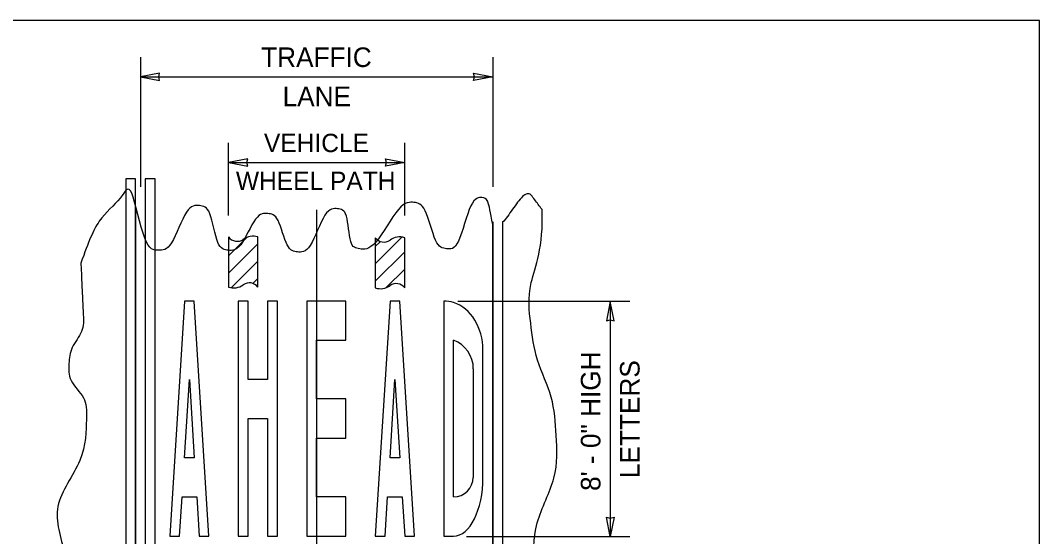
# Model space of a CAD drawing. Extents: x 99862 to 103151, y 100000 to 105076.
# Drawn here: x 102318 to 103151, y 104654 to 105076 of the extents above; entities that cross this region are included whole.
import ezdxf

# ---------------------------------------------------------------- set-up
doc = ezdxf.new("R2010")
doc.units = 0
for name, color, linetype in [('Level 1', 7, 'Continuous'), ('Level 15', 7, 'Continuous'), ('Level 2', 7, 'Continuous'), ('Level 20', 7, 'Continuous'), ('Level 3', 7, 'Continuous'), ('Level 6', 7, 'Continuous'), ('Level 60', 7, 'Continuous'), ('Level 8', 7, 'Continuous')]:
    doc.layers.add(name, color=color, linetype=linetype)

msp = doc.modelspace()

# ---------------------------------------------------------------- linework, layer by layer
at = {"layer": 'Level 1'}
msp.add_lwpolyline([(99862, 102999.5), (103151, 102999.5), (103151, 105075.5), (99862, 105075.5)], close=True, dxfattribs=at)
at = {"layer": 'Level 15'}
for p, q in [((102416.06, 105045.42), (102416.06, 104939.66)), ((102704.06, 105045.42), (102704.06, 104939.66)), ((102416.06, 105029.42), (102704.06, 105029.42)), ((102488.06, 104916.16), (102488.06, 104975.42)), ((102632.06, 104916.16), (102632.06, 104975.42)), ((102488.06, 104959.42), (102632.06, 104959.42)), ((102560.06, 104920.92), (102560.06, 104556.98)), ((102675.56, 104846.3), (102816.06, 104846.3)), ((102800.06, 104845.98), (102800.06, 104653.98)), ((102682.56, 104654), (102816.06, 104654))]:
    msp.add_line(p, q, dxfattribs=at)
for points in [[(102416.06, 105029.42), (102431.79, 105026.34), (102431.06, 105029.42), (102431.79, 105032.51)], [(102704.06, 105029.42), (102688.34, 105026.34), (102689.06, 105029.42), (102688.34, 105032.51)], [(102488.06, 104959.42), (102503.79, 104956.34), (102503.06, 104959.42), (102503.79, 104962.51)], [(102632.06, 104959.42), (102616.34, 104956.34), (102617.06, 104959.42), (102616.34, 104962.51)], [(102800.06, 104845.98), (102796.98, 104830.25), (102800.06, 104830.98), (102803.15, 104830.25)], [(102800.06, 104653.98), (102796.98, 104669.7), (102800.06, 104668.97), (102803.15, 104669.7)]]:
    msp.add_lwpolyline(points, close=True, dxfattribs=at)
at = {"layer": 'Level 2'}
for points in [[(102412.06, 104946.11), (102404.06, 104946.11), (102404.06, 104152.38)], [(102412.06, 104152.38), (102412.06, 104946.11)], [(102428.06, 104946.11), (102420.06, 104946.11), (102420.06, 104152.38)], [(102428.06, 104152.38), (102428.06, 104946.11)]]:
    msp.add_lwpolyline(points, dxfattribs=at)
at = {"layer": 'Level 3'}
msp.add_line((102704.06, 104176.2), (102704.06, 104908.92), dxfattribs=at)
for points in [[(102744.37, 104920.98), (102744.17, 104921.25), (102743.44, 104922.22), (102742.72, 104923.19), (102741.99, 104924.16), (102741.27, 104925.13), (102740.55, 104926.1), (102739.82, 104927.07), (102739.1, 104928.04), (102738.37, 104929.01), (102737.65, 104929.98), (102736.92, 104930.95), (102736.2, 104931.92), (102735.46, 104932.83), (102734.69, 104933.46), (102733.89, 104933.84), (102733.05, 104933.97), (102732.18, 104933.87), (102731.28, 104933.56), (102730.35, 104933.06), (102729.4, 104932.39), (102728.43, 104931.55), (102727.44, 104930.58), (102726.43, 104929.48), (102725.42, 104928.27), (102724.39, 104926.97), (102723.35, 104925.6), (102722.3, 104924.18), (102721.26, 104922.71), (102720.21, 104921.22), (102719.16, 104919.73), (102718.12, 104918.25), (102717.09, 104916.81), (102716.06, 104915.4), (102715.05, 104914.07), (102714.05, 104912.81), (102713.07, 104911.65), (102712.1, 104910.61), (102712.06, 104910.57)], [(102712.06, 104910.57), (102712.06, 104170.68)]]:
    msp.add_lwpolyline(points, dxfattribs=at)
for points in [[(102704.06, 104908.92), (102702.11, 104918.72), (102700.16, 104930.36), (102695.98, 104930.67), (102686.22, 104931.4), (102675.89, 104887.7), (102666.07, 104889.05), (102657.28, 104890.26), (102648.88, 104925.74), (102640.05, 104926.77), (102628.67, 104928.09), (102606.85, 104887.33), (102594.53, 104889.05), (102586.89, 104890.12), (102585.45, 104920.58), (102577.62, 104921.57), (102567.26, 104922.86), (102554.42, 104885.31), (102544.13, 104886.45), (102535.82, 104887.36), (102528.82, 104916.89), (102520.39, 104917.66), (102510.9, 104918.53), (102497.33, 104886.91), (102487.88, 104887.75), (102478.62, 104888.57), (102473.5, 104923.21), (102464.47, 104924.17), (102454.1, 104925.26), (102441.09, 104887.69), (102430.65, 104887.75), (102419.81, 104887.81), (102407.94, 104946.82), (102402.04, 104930.67), (102380.42, 104912.89), (102373.91, 104895.12), (102367.41, 104877.34)], [(102743.72, 104172.94), (102743.46, 104178.25), (102743.11, 104184.18), (102742.83, 104191.13), (102741.44, 104216.72), (102735.08, 104242.39), (102735.02, 104267.87), (102734.98, 104287.88), (102749.55, 104306.49), (102750.63, 104326.4), (102752.85, 104367.3), (102735.14, 104409.1), (102736.32, 104449.96), (102737.28, 104482.98), (102754.25, 104515.98), (102754.53, 104548.81), (102754.75, 104574.48), (102738.2, 104599.88), (102737.62, 104625.55), (102736.82, 104665.9), (102757.9, 104701.76), (102755.83, 104737.2), (102754.05, 104767.8), (102738.79, 104797.9), (102735.02, 104828.25), (102731.29, 104858.36), (102745.71, 104890.29), (102744.37, 104920.98)], [(102367.41, 104877.34), (102368.06, 104863.25), (102368.71, 104849.16), (102369.36, 104835.07), (102370, 104821.3), (102358.55, 104808.51), (102357.65, 104795.4), (102356.69, 104781.26), (102372.14, 104767.33), (102371.96, 104753.13), (102371.49, 104716.03), (102340.94, 104678.76), (102356.51, 104640.63), (102356.96, 104597.91), (102378.76, 104560.19), (102378.62, 104522.47), (102378.44, 104469.14), (102346.06, 104415.82), (102347.41, 104362.49), (102348.23, 104330.01), (102372.35, 104298.72), (102371.8, 104266.24), (102371.26, 104234.85), (102359.41, 104202.95), (102357.81, 104164.79), (102357.74, 104163.56), (102357.66, 104162.36), (102357.58, 104161.2)]]:
    msp.add_open_spline(points, degree=3, dxfattribs=at)
at = {"layer": 'Level 6'}
for p, q in [((102712.06, 104911.16), (102712.06, 104169.99)), ((102488.06, 104898.63), (102488.06, 104857.63)), ((102488.06, 104883.24), (102503.02, 104898.19)), ((102488.06, 104897.38), (102488.67, 104897.99)), ((102608.06, 104876.73), (102629.77, 104898.44)), ((102608.06, 104898.03), (102608.06, 104857.03)), ((102632.06, 104857.03), (102632.06, 104898.03)), ((102488.06, 104869.09), (102512.06, 104893.09)), ((102608.06, 104890.87), (102612.2, 104895.01)), ((102608.06, 104862.59), (102632.06, 104886.59)), ((102490.31, 104857.2), (102512.06, 104878.95)), ((102617, 104857.38), (102632.06, 104872.45)), ((102507.91, 104860.66), (102512.06, 104864.81)), ((102631.44, 104857.68), (102632.06, 104858.3))]:
    msp.add_line(p, q, dxfattribs=at)
for points in [[(102404.06, 104933.83), (102404.06, 104178.98)], [(102412.06, 104921.59), (102412.06, 104177.45)], [(102704.06, 104910.92), (102704.06, 104175.77)], [(102420.06, 104902.86), (102420.06, 104172.39)], [(102512.06, 104857.63), (102512.06, 104898.63)], [(102428.06, 104162.93), (102428.06, 104889.29)]]:
    msp.add_lwpolyline(points, dxfattribs=at)
for centre, radius, start, end in [((102495.09, 104903.78), 8.71, 216.245, 304.83036), ((102508.06, 104885.63), 13.6, 72.89727, 126.02737), ((102615.09, 104903.18), 8.71, 216.245, 304.83036), ((102628.06, 104885.03), 13.6, 72.89727, 126.02737), ((102492.13, 104870.21), 13.23, 252.07882, 306.84583), ((102505.04, 104852.48), 8.71, 36.245, 124.83036), ((102612.13, 104869.61), 13.23, 252.07882, 306.84583), ((102625.04, 104851.88), 8.71, 36.245, 124.83036)]:
    msp.add_arc(centre, radius, start, end, dxfattribs=at)
at = {"layer": 'Level 60'}
msp.add_line((103151, 105075.5), (103151, 105075.5), dxfattribs=at)
at = {"layer": 'Level 8'}
for p, q in [((102452.06, 104846.3), (102440.06, 104654.3)), ((102460.06, 104846.3), (102452.06, 104846.3)), ((102472.06, 104654.3), (102460.06, 104846.3)), ((102620.06, 104846.3), (102608.06, 104654.3)), ((102628.06, 104846.3), (102620.06, 104846.3)), ((102640.06, 104654.3), (102628.06, 104846.3)), ((102664.06, 104846.3), (102664.06, 104791.05)), ((102672.06, 104791.05), (102672.06, 104814.3)), ((102664.06, 104791.05), (102664.06, 104790.3)), ((102664.06, 104790.3), (102664.06, 104710.3)), ((102672.06, 104790.3), (102672.06, 104791.05)), ((102672.06, 104710.3), (102672.06, 104790.3)), ((102688.1, 104791.05), (102688.06, 104790.3)), ((102688.06, 104790.3), (102688.06, 104710.3)), ((102452.06, 104718.3), (102456.06, 104782.3)), ((102456.06, 104782.3), (102460.06, 104718.3)), ((102620.06, 104718.3), (102624.06, 104782.3)), ((102624.06, 104782.3), (102628.06, 104718.3)), ((102460.06, 104718.3), (102452.06, 104718.3)), ((102628.06, 104718.3), (102620.06, 104718.3)), ((102664.06, 104710.3), (102664.06, 104709.3)), ((102664.06, 104709.3), (102664.06, 104654.3)), ((102672.06, 104709.3), (102672.06, 104710.3)), ((102672.06, 104686.3), (102672.06, 104709.3)), ((102688.06, 104710.3), (102688.06, 104709.3)), ((102688.06, 104709.3), (102688.06, 104702.3)), ((102448.06, 104654.3), (102450.06, 104686.3)), ((102450.06, 104686.3), (102462.06, 104686.3)), ((102462.06, 104686.3), (102464.06, 104654.3)), ((102616.06, 104654.3), (102618.06, 104686.3)), ((102618.06, 104686.3), (102630.06, 104686.3)), ((102630.06, 104686.3), (102632.06, 104654.3)), ((102440.06, 104654.3), (102448.06, 104654.3)), ((102464.06, 104654.3), (102472.06, 104654.3)), ((102608.06, 104654.3), (102616.06, 104654.3)), ((102632.06, 104654.3), (102640.06, 104654.3)), ((102664.06, 104654.3), (102672.06, 104654.3))]:
    msp.add_line(p, q, dxfattribs=at)
for points in [[(102448.06, 104654.3), (102450.06, 104686.3), (102462.06, 104686.3), (102464.06, 104654.3), (102472.06, 104654.3), (102460.06, 104846.3), (102452.06, 104846.3), (102440.06, 104654.3), (102448.06, 104654.3)], [(102452.06, 104846.3), (102440.06, 104654.3), (102448.06, 104654.3), (102450.06, 104686.3), (102462.06, 104686.3), (102464.06, 104654.3), (102472.06, 104654.3), (102460.06, 104846.3), (102452.06, 104846.3)], [(102520.06, 104846.3), (102520.06, 104782.3), (102504.06, 104782.3), (102504.06, 104846.3), (102496.06, 104846.3), (102496.06, 104654.3), (102504.06, 104654.3), (102504.06, 104750.3), (102520.06, 104750.3), (102520.06, 104654.3), (102528.06, 104654.3), (102528.06, 104846.3), (102520.06, 104846.3)], [(102528.06, 104846.3), (102520.06, 104846.3), (102520.06, 104782.3), (102504.06, 104782.3), (102504.06, 104846.3), (102496.06, 104846.3), (102496.06, 104654.3), (102504.06, 104654.3), (102504.06, 104750.3), (102520.06, 104750.3), (102520.06, 104654.3), (102528.06, 104654.3), (102528.06, 104846.3)], [(102560.06, 104686.3), (102560.06, 104734.3), (102584.06, 104734.3), (102584.06, 104766.3), (102560.06, 104766.3), (102560.06, 104814.3), (102584.06, 104814.3), (102584.06, 104846.3), (102560.06, 104846.3), (102556.06, 104846.3), (102552.06, 104846.3), (102552.06, 104654.3), (102558.06, 104654.3), (102560.06, 104654.3), (102584.06, 104654.3), (102584.06, 104686.3), (102560.06, 104686.3)], [(102558.06, 104654.3), (102560.06, 104654.3), (102584.06, 104654.3), (102584.06, 104686.3), (102560.06, 104686.3), (102560.06, 104734.3), (102584.06, 104734.3), (102584.06, 104766.3), (102560.06, 104766.3), (102560.06, 104814.3), (102584.06, 104814.3), (102584.06, 104846.3), (102560.06, 104846.3), (102556.06, 104846.3), (102552.06, 104846.3), (102552.06, 104654.3), (102558.06, 104654.3)], [(102616.06, 104654.3), (102618.06, 104686.3), (102630.06, 104686.3), (102632.06, 104654.3), (102640.06, 104654.3), (102628.06, 104846.3), (102620.06, 104846.3), (102608.06, 104654.3), (102616.06, 104654.3)], [(102630.06, 104686.3), (102632.06, 104654.3), (102640.06, 104654.3), (102628.06, 104846.3), (102620.06, 104846.3), (102608.06, 104654.3), (102616.06, 104654.3), (102618.06, 104686.3), (102630.06, 104686.3)], [(102664.06, 104846.3), (102664.06, 104791.05), (102664.06, 104790.3), (102664.06, 104710.3), (102664.06, 104709.3), (102664.06, 104654.3), (102672.06, 104654.3)], [(102664.06, 104846.3), (102664.06, 104791.05), (102664.06, 104790.3), (102664.06, 104710.3)], [(102672.06, 104686.3), (102672.06, 104709.3), (102672.06, 104710.3), (102672.06, 104790.3), (102672.06, 104791.05), (102672.06, 104814.3)], [(102672.06, 104686.3), (102672.06, 104709.3), (102672.06, 104710.3), (102672.06, 104790.3), (102672.06, 104791.05), (102672.06, 104814.3)], [(102696.06, 104702.3), (102696.06, 104709.3), (102696.06, 104710.3), (102696.06, 104790.3), (102696.06, 104791.05), (102696.06, 104806.3)], [(102688.1, 104791.05), (102688.06, 104790.3), (102688.06, 104710.3), (102688.06, 104709.3), (102688.06, 104702.3)], [(102688.1, 104791.05), (102688.06, 104790.3), (102688.06, 104710.3), (102688.06, 104709.3), (102688.06, 104702.3)], [(102456.06, 104782.3), (102460.06, 104718.3), (102452.06, 104718.3), (102456.06, 104782.3)], [(102452.06, 104718.3), (102456.06, 104782.3), (102460.06, 104718.3), (102452.06, 104718.3)], [(102624.06, 104782.3), (102628.06, 104718.3), (102620.06, 104718.3), (102624.06, 104782.3)], [(102624.06, 104782.3), (102628.06, 104718.3), (102620.06, 104718.3), (102624.06, 104782.3)], [(102664.06, 104710.3), (102664.06, 104709.3), (102664.06, 104654.3), (102672.06, 104654.3)]]:
    msp.add_lwpolyline(points, dxfattribs=at)
for points in [[(102520.06, 104782.3), (102504.06, 104782.3), (102504.06, 104846.3), (102496.06, 104846.3), (102496.06, 104654.3), (102504.06, 104654.3), (102504.06, 104750.3), (102520.06, 104750.3), (102520.06, 104654.3), (102528.06, 104654.3), (102528.06, 104846.3), (102520.06, 104846.3)], [(102560.06, 104734.3), (102584.06, 104734.3), (102584.06, 104766.3), (102560.06, 104766.3), (102560.06, 104814.3), (102584.06, 104814.3), (102584.06, 104846.3), (102560.06, 104846.3), (102556.06, 104846.3), (102552.06, 104846.3), (102552.06, 104654.3), (102558.06, 104654.3), (102560.06, 104654.3), (102584.06, 104654.3), (102584.06, 104686.3), (102560.06, 104686.3)]]:
    msp.add_lwpolyline(points, close=True, dxfattribs=at)
msp.add_arc((102672.06, 104702.3), 16, 270, 0, dxfattribs=at)
msp.add_arc((102672.06, 104702.3), 16, 270, 0, dxfattribs=at)
for centre, major_axis, ratio, start_param, end_param in [((102664.06, 104806.3), (0, -40), 0.8, 2.888912, 3.141593), ((102664.06, 104806.3), (0, -40), 0.8, 2.888912, 3.141593), ((102664.06, 104806.3), (0, -40), 0.8, 1.570796, 2.888912), ((102664.06, 104806.3), (0, -40), 0.8, 1.570796, 2.888912), ((102670.65, 104796.02), (11.31, -16.97), 0.784465, 0.826187, 2.356194), ((102670.65, 104796.02), (11.31, -16.97), 0.784465, 0.826187, 2.356194), ((102672.06, 104702.3), (0, -48), 0.5, 0, 1.570796), ((102672.06, 104702.3), (0, -48), 0.5, 0, 1.570796)]:
    msp.add_ellipse(centre, major_axis=major_axis, ratio=ratio, start_param=start_param, end_param=end_param, dxfattribs=at)

# ---------------------------------------------------------------- texts
at = {"layer": 'Level 20'}
for s, height, rotation, p in [('TRAFFIC', 16, 360, (102514.79, 105037.42)), ('LANE', 16, 360, (102532.28, 105005.42)), ('VEHICLE', 15, 360, (102517.04, 104967.92)), ('WHEEL PATH', 15, 360, (102494.12, 104936.92)), ('8\' - 0" HIGH', 16, 90, (102792.06, 104691.22)), ('LETTERS', 16, 90, (102824.06, 104701.68))]:
    msp.add_text(s, height=height, rotation=rotation, dxfattribs=at).set_placement(p)

doc.saveas('drawing.dxf')
